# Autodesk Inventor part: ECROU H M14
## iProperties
Created: 2004-11
Part Number: ECROU H M14
Document SubType Name: Modeling
Designer: Bruno
Manufacturer: Standard
Standards Organization: Custom
Author: Bruno
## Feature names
1. Base1
